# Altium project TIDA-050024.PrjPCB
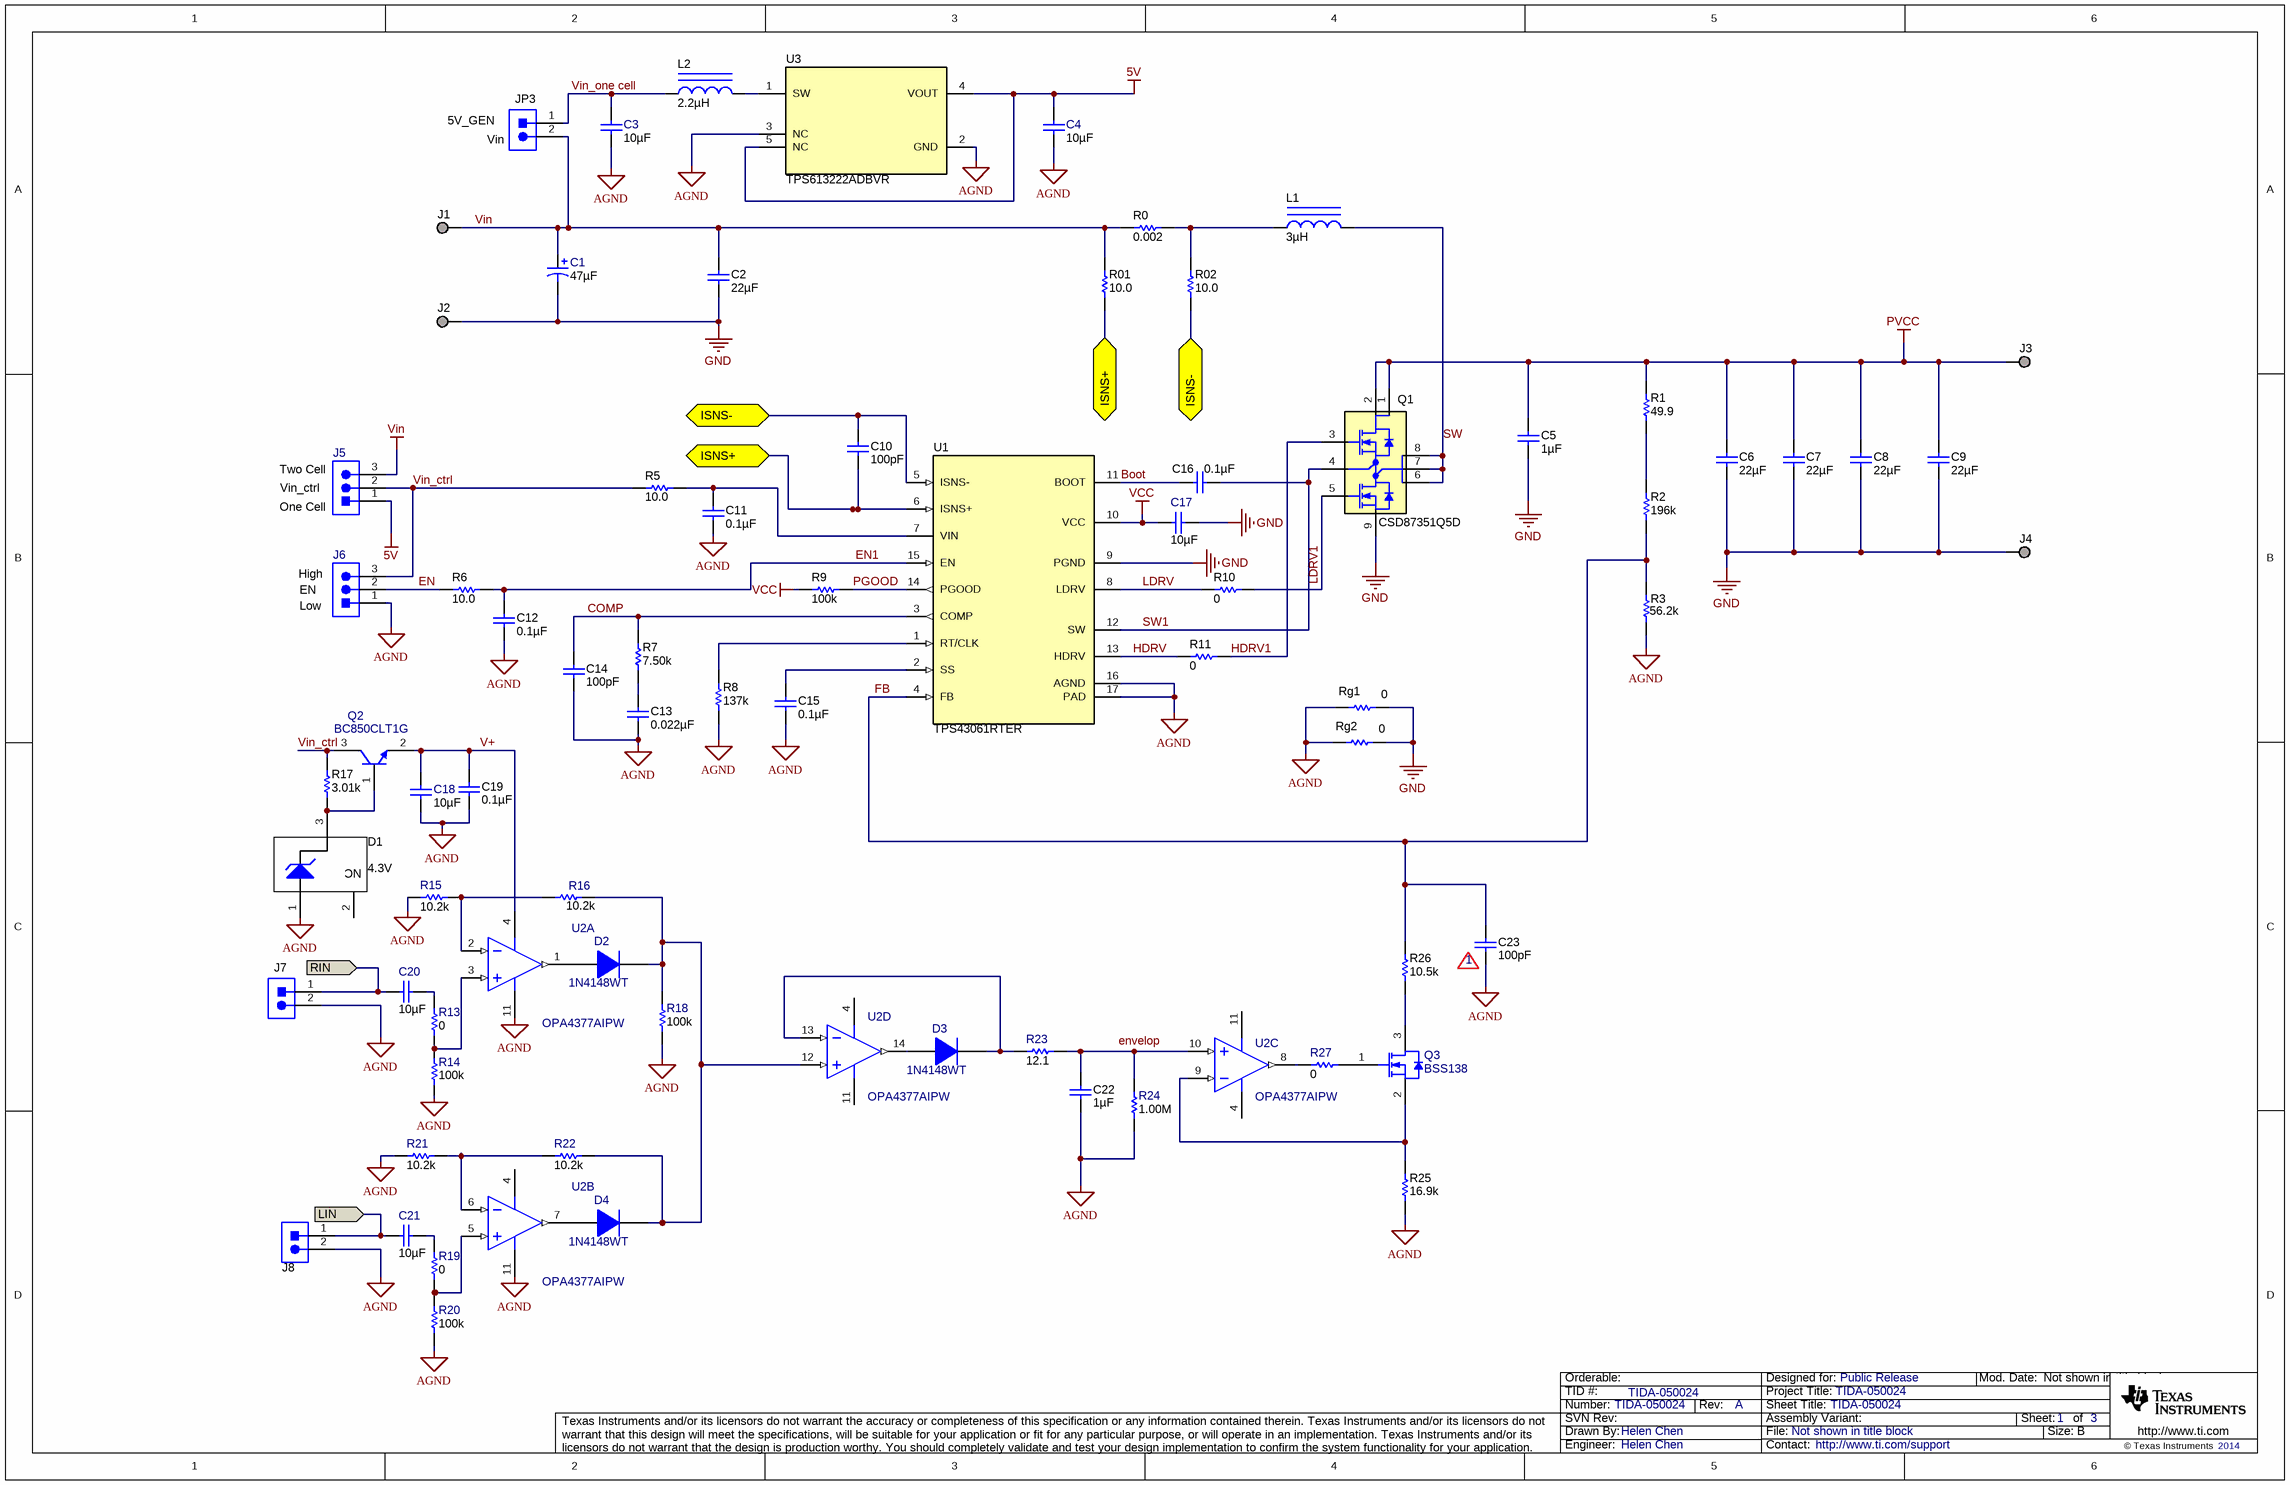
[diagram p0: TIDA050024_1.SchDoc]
TID: TIDA-050024; TechSupport: http://www.ti.com/support; SCH_Rev: A; PRJ_Title: TIDA-050024; PRJ_Number: TIDA-050024; PRJ_Engineer: Helen Chen; PRJ_Customer: Public Release; PCB_Rev: A; PCB_Layout: Helen Chen; CopyrightYear: 2014
3 sheets, 154 parts. Net scope: flat (ports and power ports of the same name join across sheets).
Board file: TIDA050024.PcbDoc
Sheets:
  TIDA050024_1.SchDoc
  TIDA050024_2.SchDoc
  TIDA050024_Hardware.SchDoc

## Sheet TIDA050024_1.SchDoc: TIDA-050024
size 431 x 279 mm; Date: Not shown in title block; ApprovedBy: Not shown in title block; CheckedBy: Not shown in title block; Author: Not shown in title block; CompanyName: TI; DrawnBy: Helen Chen; Engineer: Not shown in title block; Organization: Not shown in title block; Address1: Not shown in title block; Address2: Not shown in title block; Address3: Not shown in title block; Address4: Not shown in title block; DocumentNumber: 1; Revision: A; SheetNumber: 1; SheetTotal: 3; PageSetup: Record=PageOptions¦CenterHorizontal=True¦CenterVertical=True¦PrintScale=0.68¦XCorrection=1.00¦YCorrection=1.00¦PrintKind=0¦BorderSize=5000000¦LeftOffset=0¦BottomOffset=0¦Orientation=2¦PaperLength=1000¦PaperWidth=1000¦Scale=100¦PaperSource=15¦PrintQuality=600¦MediaType=1¦DitherType=10¦PaperKind=Letter¦PrintScaleMode=1

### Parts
C1  ValueDisplayed: 47µF  [7343-31]  (hidden comment: T495D476M025ATE120)
C2  ValueDisplayed: 22µF  [1210_270]  (hidden comment: GRM32ER61E226KE15L)
C3  ValueDisplayed: 10µF  [0603]  (hidden comment: GRM188R61E106MA73D)
C4  ValueDisplayed: 10µF  [0603]  (hidden comment: GRM188R61E106MA73D)
C5  ValueDisplayed: 1µF  [0402]  (hidden comment: C1005X5R1E105K050BC)
C6  ValueDisplayed: 22µF  [1210_270]  (hidden comment: GRM32ER61E226KE15L)
C7  ValueDisplayed: 22µF  [1210_270]  (hidden comment: GRM32ER61E226KE15L)
C8  ValueDisplayed: 22µF  [1210_270]  (hidden comment: GRM32ER61E226KE15L)
C9  ValueDisplayed: 22µF  [1210_270]  (hidden comment: GRM32ER61E226KE15L)
C10  ValueDisplayed: 100pF  [0402]  (hidden comment: GRM1555C1H101JA01D)
C11  ValueDisplayed: 0.1µF  [0402]  (hidden comment: CGA2B3X7R1H104K050BB)
C12  ValueDisplayed: 0.1µF  [0402]  (hidden comment: CGA2B3X7R1H104K050BB)
C13  ValueDisplayed: 0.022µF  [0402]  (hidden comment: GCM155R71E223KA55D)
C14  ValueDisplayed: 100pF  [0402]  (hidden comment: GRM1555C1H101JA01D)
C15  ValueDisplayed: 0.1µF  [0402]  (hidden comment: CGA2B3X7R1H104K050BB)
C16  ValueDisplayed: 0.1µF  [0402]  (hidden comment: CGA2B3X7R1H104K050BB)
C17  ValueDisplayed: 10µF  [0603]  (hidden comment: GRM188R61E106MA73D)
C18  ValueDisplayed: 10µF  [0603]  (hidden comment: GRM188R61E106MA73D)
C19  ValueDisplayed: 0.1µF  [0402]  (hidden comment: CGA2B3X7R1H104K050BB)
C20  ValueDisplayed: 10µF  [0603]  (hidden comment: GRM188R61E106MA73D)
C21  ValueDisplayed: 10µF  [0603]  (hidden comment: GRM188R61E106MA73D)
C22  ValueDisplayed: 1µF  [0402]  (hidden comment: C1005X5R1E105K050BC)
C23  ValueDisplayed: 100pF  [0402]  (hidden comment: GRM1555C1H101JA01D)
D1  value 4.3V  [SOT-23]  (hidden comment: BZX84C4V3LT1G)
D2  1N4148WT  [Fairchild_SOD-523F]
D3  1N4148WT  [Fairchild_SOD-523F]
D4  1N4148WT  [Fairchild_SOD-523F]
J1  1502-2  [Keystone1502-2]  (value not drawn)
J2  1502-2  [Keystone1502-2]  (value not drawn)
J3  1502-2  [Keystone1502-2]  (value not drawn)
J4  1502-2  [Keystone1502-2]  (value not drawn)
J5  TSW-103-07-G-S  [TSW-103-07-G-S]  (value not drawn)
J6  TSW-103-07-G-S  [TSW-103-07-G-S]  (value not drawn)
J7  TSW-102-07-G-S  [TSW-102-07-G-S]  (value not drawn)
J8  TSW-102-07-G-S  [TSW-102-07-G-S]  (value not drawn)
JP3  TSW-102-07-G-S  [TSW-102-07-G-S]  (value not drawn)
L1  ValueDisplayed: 3µH  [XAL1350]  (hidden comment: XAL1350-302MEB)
L2  ValueDisplayed: 2.2µH  [DFE252012C]  (hidden comment: DFE252012F-2R2M=P2)
Q1  CSD87351Q5D  [DQY0008A]
Q2  BC850CLT1G  [SOT-23]
Q3  BSS138  [SOT-23]
R0  ValueDisplayed: 0.002  [2512]  (hidden comment: CSNL2512FT2L00)
R01  ValueDisplayed: 10.0  [0402]  (hidden comment: CRCW040210R0FKED)
R1  ValueDisplayed: 49.9  [0402]  (hidden comment: CRCW040249R9FKED)
R02  ValueDisplayed: 10.0  [0402]  (hidden comment: CRCW040210R0FKED)
R2  ValueDisplayed: 196k  [0402]  (hidden comment: CRCW0402196KFKED)
R3  ValueDisplayed: 56.2k  [0402]  (hidden comment: CRCW040256K2FKED)
R5  ValueDisplayed: 10.0  [0402]  (hidden comment: CRCW040210R0FKED)
R6  ValueDisplayed: 10.0  [0402]  (hidden comment: CRCW040210R0FKED)
R7  ValueDisplayed: 7.50k  [0402]  (hidden comment: CRCW04027K50FKED)
R8  ValueDisplayed: 137k  [0402]  (hidden comment: CRCW0402137KFKED)
R9  ValueDisplayed: 100k  [0402]  (hidden comment: CRCW0402100KFKED)
R10  ValueDisplayed: 0  [0603]  (hidden comment: RCS06030000Z0EA)
R11  ValueDisplayed: 0  [0603]  (hidden comment: RCS06030000Z0EA)
R13  ValueDisplayed: 0  [0402]  (hidden comment: CRCW04020000Z0ED)
R14  ValueDisplayed: 100k  [0402]  (hidden comment: CRCW0402100KDHEDP)
R15  ValueDisplayed: 10.2k  [0402]  (hidden comment: CRCW040210K2FKED)
R16  ValueDisplayed: 10.2k  [0402]  (hidden comment: CRCW040210K2FKED)
R17  ValueDisplayed: 3.01k  [0402]  (hidden comment: CRCW04023K01FKED)
R18  ValueDisplayed: 100k  [0402]  (hidden comment: CRCW0402100KDHEDP)
R19  ValueDisplayed: 0  [0402]  (hidden comment: CRCW04020000Z0ED)
R20  ValueDisplayed: 100k  [0402]  (hidden comment: CRCW0402100KDHEDP)
R21  ValueDisplayed: 10.2k  [0402]  (hidden comment: CRCW040210K2FKED)
R22  ValueDisplayed: 10.2k  [0402]  (hidden comment: CRCW040210K2FKED)
R23  ValueDisplayed: 12.1  [0402]  (hidden comment: CRCW040212R1FKED)
R24  ValueDisplayed: 1.00M  [0402]  (hidden comment: ERJ-2RKF1004X)
R25  ValueDisplayed: 16.9k  [0402]  (hidden comment: CRCW040216K9FKED)
R26  ValueDisplayed: 10.5k  [0603]  (hidden comment: CRCW060310K5FKEA)
R27  ValueDisplayed: 0  [0402]  (hidden comment: CRCW04020000Z0ED)
Rg1  ValueDisplayed: 0  [0402]  (hidden comment: CRCW04020000Z0ED)
Rg2  ValueDisplayed: 0  [0402]  (hidden comment: CRCW04020000Z0ED)
U1  TPS43061RTER  [RTE0016E]
U2  OPA4377AIPW  [PW0014A_N]  (parts A,B,C,D of 4)
U3  TPS613222ADBVR  [DBV0005A_N]

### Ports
ISNS+ (bidir), ISNS- (bidir), LIN (in), RIN (in)

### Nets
5V: C4.1 J5.1 U3.4(VOUT) U3.5(NC)
AGND: C3.2 C4.2 C11.2 C12.2 C13.2 C14.2 C15.2 C18.2 C19.2 C22.2 C23.2 D1.1(A) J6.1 J7.2 J8.2 R3.1 R8.1 R14.1 R15.1 R18.1 R20.1 R21.1 R24.1 R25.1 Rg1.1 Rg2.1 U1.16(AGND) U1.17(PAD) U2.11(V-) U3.2(GND) U3.3(NC)
GND: C1.2(-) C2.2 C5.2 C6.2 C7.2 C8.2 C9.2 C17.2 J2.1 J4.1 Q1.9(PGND) Rg1.2 Rg2.2 U1.9(PGND)
PVCC: C5.1 C6.1 C7.1 C8.1 C9.1 J3.1 Q1.1(VIN) Q1.2(VIN) R1.2
VCC: C17.1 R9.1 U1.10(VCC)
Vin: C1.1(+) C2.1 J1.1 J5.3 JP3.2 R0.1 R01.2
Boot: C16.2 U1.11(BOOT)
COMP: C14.1 R7.2 U1.3(COMP)
EN: J6.2 R6.2
EN1: C12.1 R6.1 U1.15(EN)
FB: C23.1 R2.1 R3.2 R26.2 U1.4(FB)
HDRV: R11.1 U1.13(HDRV)
HDRV1: Q1.3(TG) R11.2
ISNS+: C10.2 R01.1 U1.6(ISNS+) ; port ISNS+
ISNS-: C10.1 R02.1 U1.5(ISNS-) ; port ISNS-
LDRV: R10.1 U1.8(LDRV)
LDRV1: Q1.5(BG) R10.2
LIN: C21.1 J8.1 ; port LIN
PGOOD: R9.2 U1.14(PGOOD)
RIN: C20.1 J7.1 ; port RIN
SW: L1.2 Q1.6(VSW) Q1.7(VSW) Q1.8(VSW)
SW1: C16.1 Q1.4(TGR) U1.12(SW)
V+: C18.1 C19.1 Q2.2(E) U2.4(V+)
Vin_ctrl: J5.2 J6.3 Q2.3(C) R5.2 R17.2
Vin_one cell: C3.1 JP3.1 L2.1
NetC11_1: C11.1 R5.1 U1.7(VIN)
NetC13_1: C13.1 R7.1
NetC15_1: C15.1 U1.2(SS)
NetC20_2: C20.2 R13.2
NetC21_2: C21.2 R19.2
NetC22_1: C22.1 R23.2 R24.2 U2.10(IN_C+)
NetD1_3: D1.3(K) Q2.1(B) R17.1
NetD2_1: D2.1(K) D4.1(K) R16.2 R18.2 R22.2 U2.12(IN_D+)
NetD2_2: D2.2(A) U2.1(OUT_A)
NetD3_1: D3.1(K) R23.1 U2.13(IN_D-)
NetD3_2: D3.2(A) U2.14(OUT_D)
NetD4_2: D4.2(A) U2.7(OUT_B)
NetL1_1: L1.1 R0.2 R02.2
NetL2_2: L2.2 U3.1(SW)
NetQ3_1: Q3.1(G) R27.1
NetQ3_2: Q3.2(S) R25.2 U2.9(IN_C-)
NetQ3_3: Q3.3(D) R26.1
NetR1_1: R1.1 R2.2
NetR8_2: R8.2 U1.1(RT/CLK)
NetR13_1: R13.1 R14.2 U2.3(IN_A+)
NetR15_2: R15.2 R16.1 U2.2(IN_A-)
NetR19_1: R19.1 R20.2 U2.5(IN_B+)
NetR21_2: R21.2 R22.1 U2.6(IN_B-)
NetR27_2: R27.2 U2.8(OUT_C)

Not connected (* = marked no-connect by the designer): D1 2(NC)

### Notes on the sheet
- (near JP3) 5V_GEN
- (near JP3) Vin
- (near J5) Vin_ctrl
- (near J5) One Cell
- (near J5) Two Cell
- (near J6) High
- (near J6) EN
- (near J6) Low
- (near C23) 1
- Labels drawn without touching a wire or pin: envelop

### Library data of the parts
C1 = T495D476M025ATE120: CAP, TA, 47 µF, 25 V, +/- 20%, 0.12 ohm, SMD; Manufacturer: Kemet; Polarized: Y; CompType: Capacitor; Value: 47uF; U/M: EA; Cap_F: 0.000047; Tolerance_%: 20; VDC_V: 25; Value2: 25V; ESR_ohm: 0.12; IRMS_A: 1.006; TaMin_C: -55; TaMax_C: 125; Cap_Case: D; AEC Category: Q200
C2 C6-C9 = GRM32ER61E226KE15L: CAP, CERM, 22 µF, 25 V, +/- 10%, X5R, 1210; Manufacturer: MuRata; Polarized: N; CompType: Capacitor; Value: 22uF; U/M: EA; Cap_F: 0.000022; Tolerance_%: 10; ESR_ohm: 0.002; Value1: 0.002 ohm; VDC_V: 25; Value2: 25V; IRMS_A: 3.67; TaMin_C: -55; TaMax_C: 85; Cap_Case: 1210; SizeArea_mm2: 8; SizeAreaWB_mm2: 14.7; SizeX_mm: 3.2; SizeY_mm: 2.5; SizeZ_mm: 2.7; AEC Category: Q200
C3 C4 C17 C18 C20 C21 = GRM188R61E106MA73D: CAP, CERM, 10 µF, 25 V, +/- 20%, X5R, 0603; Manufacturer: MuRata; Polarized: N; CompType: Capacitor; Value: 10uF; U/M: EA; Cap_F: 0.00001; Tolerance_%: 20; Value1: Unknown; VDC_V: 25; Value2: 25V; TaMin_C: -55; TaMax_C: 85; AEC Category: Q200
C5 C22 = C1005X5R1E105K050BC: CAP, CERM, 1 µF, 25 V,+/- 10%, X5R, 0402; Manufacturer: TDK; Polarized: N; CompType: Capacitor; Value: 1uF; U/M: EA; Cap_F: 0.000001; Tolerance_%: 10; VDC_V: 25; Value2: 25V; TaMin_C: -55; TaMax_C: 80; SizeArea_mm2: 0.5; SizeAreaWB_mm2: 3; SizeX_mm: 1; SizeZ_mm: 0.6; AEC Category: Q200; Green_Lifecycle: Active; Green_REACh: Passed
C10 C14 C23 = GRM1555C1H101JA01D: CAP, CERM, 100 pF, 50 V,+/- 5%, C0G/NP0, 0402; Manufacturer: MuRata; Polarized: N; CompType: Capacitor; Value: 100pF; U/M: EA; Cap_F: 0.0000000001; Tolerance_%: 5; VDC_V: 50; Value2: 50V; TaMin_C: -55; TaMax_C: 125; SizeArea_mm2: 0.5; SizeAreaWB_mm2: 3; SizeX_mm: 1; SizeZ_mm: 0.6; AEC Category: Q200; Green_Lifecycle: Active; Green_REACh: Passed
C11 C12 C15 C16 C19 = CGA2B3X7R1H104K050BB: CAP, CERM, 0.1 µF, 50 V,+/- 10%, X7R, AEC-Q200 Grade 1, 0402; Manufacturer: TDK; Polarized: N; CompType: Capacitor; Value: 0.1uF; U/M: EA; Cap_F: 0.0000001; Tolerance_%: 10; ESR_ohm: 0.039064; Value1: 0.039064 ohm; VDC_V: 50; Value2: 50V; IRMS_A: 0.814669; TaMin_C: -55; TaMax_C: 125; SizeArea_mm2: 0.5; SizeAreaWB_mm2: 3; SizeX_mm: 1; SizeZ_mm: 0.6; AEC Category: Q200; AEC Qualified: Y; Green_Lifecycle: Active; Green_REACh: Passed
C13 = GCM155R71E223KA55D: CAP, CERM, 0.022 µF, 25 V,+/- 10%, X7R, AEC-Q200 Grade 1, 0402; Manufacturer: MuRata; Polarized: N; CompType: Capacitor; Value: 0.022uF; U/M: EA; Cap_F: 0.000000022; Tolerance_%: 10; VDC_V: 25; Value2: 25V; TaMin_C: -55; TaMax_C: 125; SizeArea_mm2: 0.5; SizeAreaWB_mm2: 3; SizeX_mm: 1; SizeZ_mm: 0.6; AEC Category: Q200; AEC Qualified: Y
D1 = BZX84C4V3LT1G: Diode, Zener, 4.3 V, 225 mW, SOT-23; Manufacturer: ON Semiconductor; U/M: EA; Power_W: 0.225; Vz_V: 4.3; Value1: 0.225W; RJA_CperW: 556; SizeAreaWB_mm2: 14; SizeArea_mm2: 7.5; SizeX_mm: 2.5; SizeY_mm: 3; SizeZ_mm: 1.1; AEC Category: Q101
D2-D4 = 1N4148WT: Diode, Switching, 75 V, 0.3 A, SMD, 2-Leads, Body 1.2x0.8mm; Manufacturer: Fairchild Semiconductor; U/M: EA; Value: 75V; Value1: 0.3A; Io_A: 0.3; Vr_V: 75; TJmax_C: 150
J1-J4 = CMP-0055113-1: Terminal, Turret, TH, Double; Manufacturer: Keystone; CT: FALSE; Green_REACh: Passed; CompType: Turret Terminal; Green_Lifecycle: Active
J5 J6 = TSW-103-07-G-S: Header, 100mil, 3x1, Gold, TH; Manufacturer: Samtec; SymbolCreator: a0799628; U/M: EA
J7 J8 JP3 = TSW-102-07-G-S: Header, 100mil, 2x1, Gold, TH; Manufacturer: Samtec; SymbolCreator: a0412235; Pitch_mm: 2.54; Gender: Male; Shrouded: N; Row_Count: 1; Current_A: 6.3; Voltage_V: 550; Cert_CSA: Y
L1 = XAL1350-302MEB: Inductor, Shielded, Composite, 3 µH, 21 A, 0.0059 ohm, SMD; Manufacturer: Coilcraft; Value: 3uH; Ind_H: 3.0E-6; Imax_A: 21; Irms: 21A @ 40C rise; Isat: 37A @ 30% inductance drop; DCR_ohm: 0.0059; Value2: 21A; SizeAreaWB_mm2: 240; SizeArea_mm2: 182; SizeX_mm: 13; SizeY_mm: 14; SizeZ_mm: 5; AEC Category: Q200; AEC Qualified: N
L2 = DFE252012F-2R2M=P2: Inductor, Shielded, Powdered Iron, 2.2 µH, 2.3 A, 0.082 ohm, SMD; Manufacturer: MuRata Toko; Value: 2.2uH; Ind_H: 2.2E-6; Imax_A: 2.3; Irms: 2.3A @ 40C rise; Isat: 3.3A @ 30% inductance drop; DCR_ohm: 0.082; Value2: 2.3A; SizeAreaWB_mm2: 11.84; SizeArea_mm2: 5.94; SizeX_mm: 2.7; SizeY_mm: 2.2; SizeZ_mm: 1.2; AEC Category: Q200; AEC Qualified: N
Q1 = CSD87351Q5D: MOSFET, 2-CH, N-CH, 30 V, 35 A, DQY0008A (LSON-CLIP-8); Manufacturer: Texas Instruments; Alternate Manufacturer: None; SymbolCreator: a0799628; U/M: EA; ChType: N; Value: 30V; VdsMax_V: 30; Value1: 0.0088 ohm; Rdson45_ohm: 0.0088; Value2: 5.9 nC; QgTyp_nC: 5.9; Vgs_V: 10; IdsMax_A: 35; SizeAreaWB_mm2: 56; SizeX_mm: 6; SizeY_mm: 5; SizeZ_mm: 1.6; AEC Category: Q101
Q2 = BC850CLT1G, ON Semiconductor: Transistor, NPN, 45 V, 0.1 A, SOT-23; CompType: BJT; PNP: 0; NPN: 1; Vceo_V: 45; Vcesat1_V: 0.7; Value: 45 V; IcRated_A: 0.1; Value1: 0.1 A; HfeMax: 800; TaMin_C: -55; TaMax_C: 150; U/M: EA
Q3 = BSS138: MOSFET, N-CH, 50 V, 0.22 A, SOT-23; Manufacturer: Fairchild Semiconductor; Alternate Manufacturer: None; U/M: EA; ChType: N; Value: 50V; VdsMax_V: 50; Value1: 6 ohm; Rdson45_ohm: 6; Value2: 1.7 nC; QgTyp_nC: 1.7; Vgs_V: 20; IdsMax_A: 0.22
R0 = CSNL2512FT2L00: RES, 0.002, 1%, 2 W, 2512; Manufacturer: Stackpole Electronics Inc; CompType: Resistor; Value: 0.002; Value_Code: 2L000; Tolerance_%: 1; Power_W: 2; Value2: 2W; VDC_V: 200; TempCo: 50 ppm/C; SizeArea_mm2: 20.16; SizeX_mm: 6.3; SizeY_mm: 3.2; SizeZ_mm: 0.71; U/M: EA; AEC Category: Q200
R01 R02 R5 R6 = CRCW040210R0FKED: RES, 10.0, 1%, 0.063 W, 0402; Manufacturer: Vishay-Dale; CompType: Resistor; Value: 10.0; Res_ohm: 10; Value_Code: 10R0; Tolerance_%: 1; Power_W: 0.063; Value2: 0.063W; VDC_V: 50; TempCo: 100 ppm/C; SizeArea_mm2: 0.5; SizeZ_mm: 0.6; EIA_Code: E96; U/M: EA; AEC Category: Q200; Green_Lifecycle: Active; Green_REACh: Passed
R1 = CRCW040249R9FKED: RES, 49.9, 1%, 0.063 W, 0402; Manufacturer: Vishay-Dale; CompType: Resistor; Value: 49.9; Value_Code: 49R9; Tolerance_%: 1; Power_W: 0.063; Value2: 0.063W; VDC_V: 50; TempCo: 100 ppm/C; SizeArea_mm2: 0.5; SizeZ_mm: 0.6; EIA_Code: E96; U/M: EA; AEC Category: Q200; Green_Lifecycle: Active; Green_REACh: Passed
R2 = CRCW0402196KFKED: RES, 196 k, 1%, 0.063 W, 0402; Manufacturer: Vishay-Dale; CompType: Resistor; Value: 196k; Res_ohm: 196000; Tolerance_%: 1; Power_W: 0.063; Value2: 0.063W; VDC_V: 50; TempCo: 100 ppm/C; SizeArea_mm2: 0.5; SizeZ_mm: 0.6; EIA_Code: E96; U/M: EA; AEC Category: Q200; Green_Lifecycle: Active; Green_REACh: Passed
R3 = CRCW040256K2FKED: RES, 56.2 k, 1%, 0.063 W, 0402; Manufacturer: Vishay-Dale; CompType: Resistor; Value: 56.2k; Res_ohm: 56200; Value_Code: 56k2; Tolerance_%: 1; Power_W: 0.063; Value2: 0.063W; VDC_V: 50; TempCo: 100 ppm/C; SizeArea_mm2: 0.5; SizeZ_mm: 0.6; EIA_Code: E96; U/M: EA; AEC Category: Q200; Green_Lifecycle: Active; Green_REACh: Passed
R7 = CRCW04027K50FKED: RES, 7.50 k, 1%, 0.063 W, 0402; Manufacturer: Vishay-Dale; CompType: Resistor; Value: 7.50k; Res_ohm: 7500; Value_Code: 7k50; Tolerance_%: 1; Power_W: 0.063; Value2: 0.063W; VDC_V: 50; TempCo: 100 ppm/C; SizeArea_mm2: 0.5; SizeZ_mm: 0.6; EIA_Code: E96; U/M: EA; AEC Category: Q200; Green_Lifecycle: Active; Green_REACh: Passed
R8 = CRCW0402137KFKED: RES, 137 k, 1%, 0.063 W, 0402; Manufacturer: Vishay-Dale; CompType: Resistor; Value: 137k; Res_ohm: 137000; Tolerance_%: 1; Power_W: 0.063; Value2: 0.063W; VDC_V: 50; TempCo: 100 ppm/C; SizeArea_mm2: 0.5; SizeZ_mm: 0.6; EIA_Code: E96; U/M: EA; AEC Category: Q200; Green_Lifecycle: Active; Green_REACh: Passed
R9 = CRCW0402100KFKED: RES, 100 k, 1%, 0.063 W, 0402; Manufacturer: Vishay-Dale; CompType: Resistor; Value: 100k; Res_ohm: 100000; Tolerance_%: 1; Power_W: 0.063; Value2: 0.063W; VDC_V: 50; TempCo: 100 ppm/C; SizeArea_mm2: 0.5; SizeZ_mm: 0.6; EIA_Code: E96; U/M: EA; AEC Category: Q200; Green_Lifecycle: Active; Green_REACh: Passed
R10 = CMP-0081973-1: RES, 0, 0%, 0.25 W, AEC-Q200 Grade 0, 0603; Manufacturer: Vishay-Dale; SizeAreaWB_mm2: 4.68; SizeArea_mm2: 1.28; AEC Qualified: Y; AEC Category: Q200; Value: 0; SizeZ_mm: 1; SizeY_mm: 0.8; Power_W: 250mW; Value2: 0.25W; CompType: Resistor; SizeX_mm: 1.6
R11 = CMP-0081973-1: RES, 0, 0%, 0.25 W, AEC-Q200 Grade 0, 0603; Manufacturer: Vishay-Dale; SizeAreaWB_mm2: 4.68; SizeArea_mm2: 1.28; AEC Qualified: Y; AEC Category: Q200; Value: 0; SizeZ_mm: 1; SizeY_mm: 0.8; Power_W: 250mW; Value2: 0.25W; SizeX_mm: 1.6
R13 R19 R27 = CRCW04020000Z0ED: RES, 0, 5%, 0.063 W, 0402; Manufacturer: Vishay-Dale; CompType: Resistor; Value: 0; Value_Code: 0000; Tolerance_%: 5; Power_W: 0.063; Value2: 0.063W; VDC_V: 50; TempCo: 200 ppm/C; EIA_Code: E24; U/M: EA
R14 R18 R20 = CRCW0402100KDHEDP: RES, 100 k, 0.5%, 0.063 W, 0402; Manufacturer: Vishay-Dale; CompType: Resistor; Value: 100k; Res_ohm: 100000; Tolerance_%: 0.5; Power_W: 0.063; Value2: 0.063W; VDC_V: 50; TempCo: 50 ppm/C; EIA_Code: E192; U/M: EA
R15 R16 R21 R22 = CRCW040210K2FKED: RES, 10.2 k, 1%, 0.063 W, 0402; Manufacturer: Vishay-Dale; CompType: Resistor; Value: 10.2k; Res_ohm: 10200; Value_Code: 10k2; Tolerance_%: 1; Power_W: 0.063; Value2: 0.063W; VDC_V: 50; TempCo: 100 ppm/C; EIA_Code: E96; U/M: EA
R17 = CRCW04023K01FKED: RES, 3.01 k, 1%, 0.063 W, 0402; Manufacturer: Vishay-Dale; CompType: Resistor; Value: 3.01k; Res_ohm: 3010; Value_Code: 3k01; Tolerance_%: 1; Power_W: 0.063; Value2: 0.063W; VDC_V: 50; TempCo: 100 ppm/C; SizeArea_mm2: 0.5; SizeZ_mm: 0.6; EIA_Code: E96; U/M: EA; AEC Category: Q200
R23 = CRCW040212R1FKED: RES, 12.1, 1%, 0.063 W, 0402; Manufacturer: Vishay-Dale; CompType: Resistor; Value: 12.1; Value_Code: 12R1; Tolerance_%: 1; Power_W: 0.063; Value2: 0.063W; VDC_V: 50; TempCo: 100 ppm/C; EIA_Code: E96; U/M: EA
R24 = ERJ-2RKF1004X: RES, 1.00 M, 1%, 0.1 W, 0402; Manufacturer: Panasonic; CompType: Resistor; Value: 1.00Meg; Res_ohm: 1000000; Value_Code: 1M00; Tolerance_%: 1; Power_W: 0.1; Value2: 0.1W; VDC_V: 50; TempCo: 100 ppm/C; EIA_Code: E96; U/M: EA
R25 = CRCW040216K9FKED: RES, 16.9 k, 1%, 0.063 W, 0402; Manufacturer: Vishay-Dale; CompType: Resistor; Value: 16.9k; Res_ohm: 16900; Value_Code: 16k9; Tolerance_%: 1; Power_W: 0.063; Value2: 0.063W; VDC_V: 50; TempCo: 100 ppm/C; SizeArea_mm2: 0.5; SizeZ_mm: 0.6; EIA_Code: E96; U/M: EA; AEC Category: Q200
R26 = CRCW060310K5FKEA: RES, 10.5 k, 1%, 0.1 W, 0603; Manufacturer: Vishay-Dale; CompType: Resistor; Value: 10.5k; Res_ohm: 10500; Value_Code: 10k5; Tolerance_%: 1; Power_W: 0.1; Value2: 0.1W; VDC_V: 75; TempCo: 100 ppm/C; SizeArea_mm2: 1.28; SizeX_mm: 1.6; SizeY_mm: 0.8; EIA_Code: E96; U/M: EA; AEC Category: Q200; Green_Lifecycle: Active; Green_REACh: Passed
Rg1 Rg2 = CRCW04020000Z0ED: RES, 0, 5%, 0.063 W, 0402; Manufacturer: Vishay-Dale; CompType: Resistor; Value: 0; Value_Code: 0000; Tolerance_%: 5; Power_W: 0.063; Value2: 0.063W; VDC_V: 50; TempCo: 200 ppm/C; SizeArea_mm2: 0.5; SizeX_mm: 1; SizeZ_mm: 0.6; EIA_Code: E24; U/M: EA; AEC Category: Q200; Green_Lifecycle: Active; Green_REACh: Passed
U1 = CMP-0067158-1: Low Iq, Synchronous Boost Controller with Wide Input Voltage and 5.5V Gate Drive for Low Qg  NexFETs, RTE0016E (WQFN-16); Alternate PartNumber: TPS43061RTET; Alternate Manufacturer: Texas Instruments; Green_Lifecycle: Active; SizeAreaWB_mm2: 16.0; Green_REACh: Passed; U/M: EA; SizeZ_mm: 0.8; SizeX_mm: 3.0; SizeArea_mm2: 9.0; CompType: IC
U2 = OPA4377AIPW: Low-Cost, Low Noise, 5.5 MHz CMOS Operational Amplifier, 2.2 to 5.5 V, -40 to 125 degC, 14-pin SOP (PW0014A), Green (RoHS & no Sb/Br); Manufacturer: Texas Instruments; Alternate Manufacturer: None; Alternate PartNumber: Equivalent; CMRR(Min)(dB): 70; IIB(Max)(pA): 10; Iq per channel(Max)(mA): 1.05; Number of Channels: 4; Offset Drift(Typ)(uV/C): 0.32; Slew Rate(Typ)(V/us): 2; Sub Family: Low Input Bias Current Amp (<=10pA), Low Noise Amp (<=10nV/rtHz), Low Supply Voltage Amplifier (<=2.7V), Precision Amplifier; Total Supply Voltage(Max)(+5V is 5, +/-5V is 10): 5.5; Total Supply Voltage(Min)(+5V is 5, +/-5V is 10): 2.2; Vio (25C)(Max)(mV): 1; Vn at 1kHz(Typ)(nV/rtHz): 7.5
U3 = CMP-0079087-1: 6.5-μA Quiescent Current, 1.8-A Switch Current Boost Converter, DBV0005A (SOT-23-5); Alternate PartNumber: TPS613222ADBVT; Alternate Manufacturer: Texas Instruments; SizeAreaWB_mm2: 14.82; SizeZ_mm: 1.45; SizeX_mm: 2.8; SizeY_mm: 2.9; SizeArea_mm2: 8.12; CompType: IC; AEC Qualified: N; AEC Category: Q200

## Sheet TIDA050024_2.SchDoc: TIDA-050024
size 431 x 279 mm; Date: Not shown in title block; ApprovedBy: Not shown in title block; CheckedBy: Not shown in title block; Author: Not shown in title block; CompanyName: TI; DrawnBy: Helen Chen; Engineer: Not shown in title block; Organization: Not shown in title block; Address1: Not shown in title block; Address2: Not shown in title block; Address3: Not shown in title block; Address4: Not shown in title block; DocumentNumber: PMP15036; Revision: A; SheetNumber: 2; SheetTotal: 3; PageSetup: Record=PageOptions¦CenterHorizontal=True¦CenterVertical=True¦PrintScale=0.68¦XCorrection=1.00¦YCorrection=1.00¦PrintKind=0¦BorderSize=5000000¦LeftOffset=0¦BottomOffset=0¦Orientation=2¦PaperLength=1000¦PaperWidth=1000¦Scale=100¦PaperSource=15¦PrintQuality=-3¦MediaType=1¦DitherType=10¦PrintScaleMode=1¦PaperKind=A1 (594 x 841mm)¦PaperIndex=124
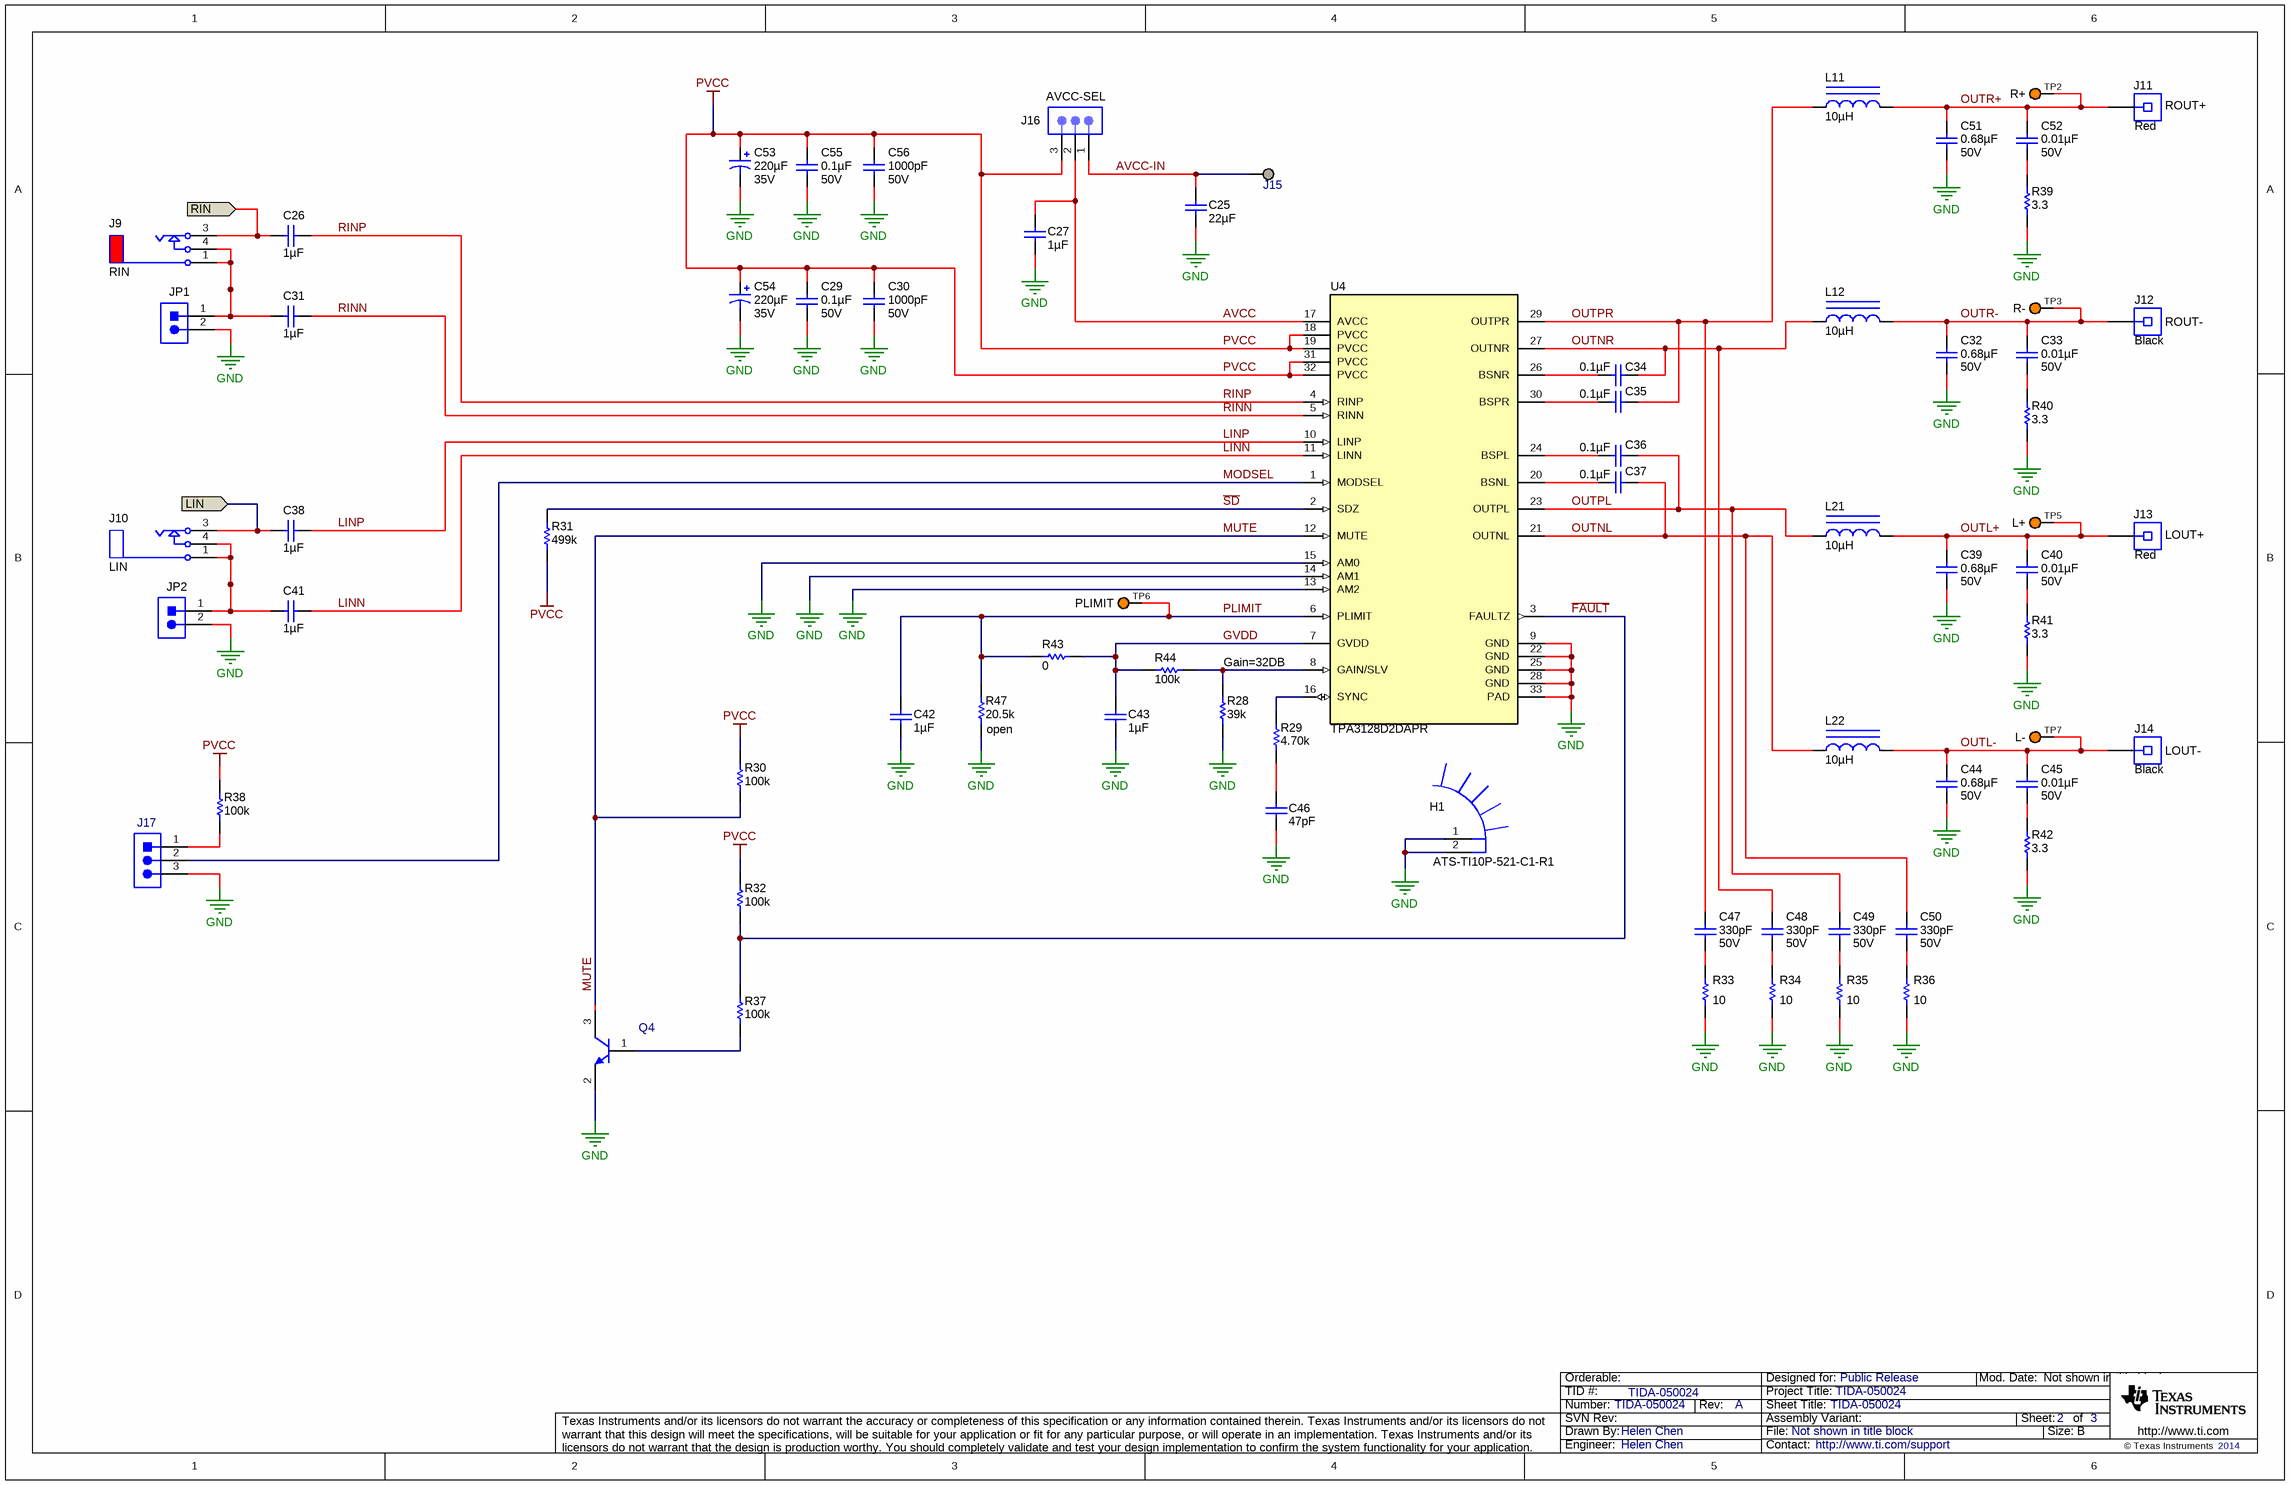
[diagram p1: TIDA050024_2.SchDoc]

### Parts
(Parts that share a designator on the sheet are numbered #1, #2 ... from top to bottom, then left to right.)
C25  ValueDisplayed: 22µF  [1210_270]  (hidden comment: GRM32ER61E226KE15L)
C26  ValueDisplayed: 1µF  [0603]  (hidden comment: GRM188R61E105KA12D)
C27  ValueDisplayed: 1µF  [0603]  (hidden comment: GRM188R61E105KA12D)
C29  ValueDisplayed: 0.1µF  Value2: 50V  [0603L]  (hidden comment: GCM188R71H104KA57D)
C30  ValueDisplayed: 1000pF  Value2: 50V  [0603L]  (hidden comment: GRM1885C1H102JA01D)
C31  ValueDisplayed: 1µF  [0603]  (hidden comment: GRM188R61E105KA12D)
C32  ValueDisplayed: 0.68µF  Value2: 50V  [1206L]  (hidden comment: GRM31MR71H684KA88L)
C33  ValueDisplayed: 0.01µF  Value2: 50V  [0603L]  (hidden comment: GRM188R71H103KA01D)
C34  ValueDisplayed: 0.1µF  [0603L]  (hidden comment: GCM188R71H104KA57D)
C35  ValueDisplayed: 0.1µF  [0603L]  (hidden comment: GCM188R71H104KA57D)
C36  ValueDisplayed: 0.1µF  [0603L]  (hidden comment: GCM188R71H104KA57D)
C37  ValueDisplayed: 0.1µF  [0603L]  (hidden comment: GCM188R71H104KA57D)
C38  ValueDisplayed: 1µF  [0603]  (hidden comment: GRM188R61E105KA12D)
C39  ValueDisplayed: 0.68µF  Value2: 50V  [1206L]  (hidden comment: GRM31MR71H684KA88L)
C40  ValueDisplayed: 0.01µF  Value2: 50V  [0603L]  (hidden comment: GRM188R71H103KA01D)
C41  ValueDisplayed: 1µF  [0603]  (hidden comment: GRM188R61E105KA12D)
C42  ValueDisplayed: 1µF  [0603]  (hidden comment: GRM188R61E105KA12D)
C43  ValueDisplayed: 1µF  [0603]  (hidden comment: GRM188R61E105KA12D)
C44  ValueDisplayed: 0.68µF  Value2: 50V  [1206L]  (hidden comment: GRM31MR71H684KA88L)
C45  ValueDisplayed: 0.01µF  Value2: 50V  [0603L]  (hidden comment: GRM188R71H103KA01D)
C46  ValueDisplayed: 47pF  [0603L]  (hidden comment: GRM1885C1H470JA01D)
C47  ValueDisplayed: 330pF  Value2: 50V  [0603L]  (hidden comment: GRM1885C1H331JA01D)
C48  ValueDisplayed: 330pF  Value2: 50V  [0603L]  (hidden comment: GRM1885C1H331JA01D)
C49  ValueDisplayed: 330pF  Value2: 50V  [0603L]  (hidden comment: GRM1885C1H331JA01D)
C50  ValueDisplayed: 330pF  Value2: 50V  [0603L]  (hidden comment: GRM1885C1H331JA01D)
C51  ValueDisplayed: 0.68µF  Value2: 50V  [1206L]  (hidden comment: GRM31MR71H684KA88L)
C52  ValueDisplayed: 0.01µF  Value2: 50V  [0603L]  (hidden comment: GRM188R71H103KA01D)
C53  ValueDisplayed: 220µF  Value2: 35V  [FC_1000x1250]  (hidden comment: EEU-FC1V221)
C54  ValueDisplayed: 220µF  Value2: 35V  [FC_1000x1250]  (hidden comment: EEU-FC1V221)
C55  ValueDisplayed: 0.1µF  Value2: 50V  [0603L]  (hidden comment: GCM188R71H104KA57D)
C56  ValueDisplayed: 1000pF  Value2: 50V  [0603L]  (hidden comment: GRM1885C1H102JA01D)
H1#1  ATS-TI10P-521-C1-R1  [HSINK_ATS-TI10P-521-C1-R1]
J9  RIN  [Keystone_971]
J10  LIN  [Keystone_970]
J11  ROUT+  Shell Color: Red  [Keystone_7006]
J12  ROUT-  Shell Color: Black  [Keystone_7007]
J13  LOUT+  Shell Color: Red  [Keystone_7006]
J14  LOUT-  Shell Color: Black  [Keystone_7007]
J15  Suggest using a net name here  [Keystone1502-2]  (value not drawn)
J16  AVCC-SEL  [PBC03SAAN]
J17  TSW-103-07-G-S  [TSW-103-07-G-S]  (value not drawn)
JP1  TSW-102-07-G-S  [TSW-102-07-G-S]  (value not drawn)
JP2  TSW-102-07-G-S  [TSW-102-07-G-S]  (value not drawn)
L11  ValueDisplayed: 10µH  [SRT8045]  (hidden comment: SRT8045-103MEB)
L12  ValueDisplayed: 10µH  [SRT8045]  (hidden comment: SRT8045-103MEB)
L21  ValueDisplayed: 10µH  [SRT8045]  (hidden comment: SRT8045-103MEB)
L22  ValueDisplayed: 10µH  [SRT8045]  (hidden comment: SRT8045-103MEB)
Q4  BC850CLT1G  [SOT-23]  (value not drawn)
R28  ValueDisplayed: 39k  [0402]  (hidden comment: CRCW040239K0JNED)
R29  ValueDisplayed: 4.70k  [0603L]  (hidden comment: RG1608P-472-B-T5)
R30  value 100k  [0603L]  (hidden comment: RC0603FR-07100KL)
R31  ValueDisplayed: 499k  [0603L]  (hidden comment: RC0603FR-07499KL)
R32  value 100k  [0603L]  (hidden comment: RC0603FR-07100KL)
R33  ValueDisplayed: 10  [0805_KTR]  (hidden comment: CRCW080510R0JNEA)
R34  ValueDisplayed: 10  [0805_KTR]  (hidden comment: CRCW080510R0JNEA)
R35  ValueDisplayed: 10  [0805_KTR]  (hidden comment: CRCW080510R0JNEA)
R36  ValueDisplayed: 10  [0805_KTR]  (hidden comment: CRCW080510R0JNEA)
R37  value 100k  [0603L]  (hidden comment: RC0603FR-07100KL)
R38  value 100k  [0603L]  (hidden comment: RC0603FR-07100KL)
R39  ValueDisplayed: 3.3  [0603L]  (hidden comment: CRCW06033R30JNEA)
R40  ValueDisplayed: 3.3  [0603L]  (hidden comment: CRCW06033R30JNEA)
R41  ValueDisplayed: 3.3  [0603L]  (hidden comment: CRCW06033R30JNEA)
R42  ValueDisplayed: 3.3  [0603L]  (hidden comment: CRCW06033R30JNEA)
R43  ValueDisplayed: 0  [0402]  (hidden comment: ERJ-2GE0R00X)
R44  value 100k  [0603L]  (hidden comment: RC0603FR-07100KL)
R47  ValueDisplayed: 20.5k  [0402]  (hidden comment: CRCW040220K5FKED)
TP2  R+  [Keystone5003]
TP3  R-  [Keystone5003]
TP5  L+  [Keystone5003]
TP6  PLIMIT  [Keystone5003]
TP7  L-  [Keystone5003]
U4  TPA3128D2DAPR  [DAP0032A_N]

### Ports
LIN (in), RIN (in)

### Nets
GND: C25.2 C27.2 C29.1 C30.1 C32.2 C39.2 C42.1 C43.1 C44.2 C46.2 C51.2 C53.2(-) C54.2(-) C55.1 C56.1 H1#1.1 H1#1.2 J17.3 JP1.2 JP2.2 Q4.2(E) R28.1 R33.1 R34.1 R35.1 R36.1 R39.1 R40.1 R41.1 R42.1 R47.1 U4.9(GND) U4.13(AM2) U4.14(AM1) U4.15(AM0) U4.22(GND) U4.25(GND) U4.28(GND) U4.33(PAD)
PVCC: C29.2 C30.2 C53.1(+) C54.1(+) C55.2 C56.2 J16.3 R30.1 R31.2 R32.1 R38.2 U4.18(PVCC) U4.19(PVCC) U4.31(PVCC) U4.32(PVCC)
~{FAULT}: R32.2 R37.1 U4.3(FAULTZ)
~{SD}: R31.1 U4.2(SDZ)
AVCC: C27.1 J16.2 U4.17(AVCC)
AVCC-IN: C25.1 J15.1 J16.1
GVDD: C43.2 R43.2 R44.1 U4.7(GVDD)
LIN: C38.1 J10.3(TIP) ; port LIN
LINN: C41.2 U4.11(LINN)
LINP: C38.2 U4.10(LINP)
MODSEL: J17.2 U4.1(MODSEL)
MUTE: Q4.3(C) R30.2 U4.12(MUTE)
OUTL+: C39.1 C40.1 J13.1 L21.2 TP5.1
OUTL-: C44.1 C45.1 J14.1 L22.2 TP7.1
OUTNL: C37.1 C50.2 L22.1 U4.21(OUTNL)
OUTNR: C34.1 C48.2 L12.1 U4.27(OUTNR)
OUTPL: C36.1 C49.2 L21.1 U4.23(OUTPL)
OUTPR: C35.1 C47.2 L11.1 U4.29(OUTPR)
OUTR+: C51.1 C52.1 J11.1 L11.2 TP2.1
OUTR-: C32.1 C33.1 J12.1 L12.2 TP3.1
PLIMIT: C42.2 R43.1 R47.2 TP6.1 U4.6(PLIMIT)
RIN: C26.1 J9.3(TIP) ; port RIN
RINN: C31.2 U4.5(RINN)
RINP: C26.2 U4.4(RINP)
NetC31_1: C31.1 J9.1(SLEEVE) J9.4(TIP_SWITCH) JP1.1
NetC33_2: C33.2 R40.2
NetC34_2: C34.2 U4.26(BSNR)
NetC35_2: C35.2 U4.30(BSPR)
NetC36_2: C36.2 U4.24(BSPL)
NetC37_2: C37.2 U4.20(BSNL)
NetC40_2: C40.2 R41.2
NetC41_1: C41.1 J10.1(SLEEVE) J10.4(TIP_SWITCH) JP2.1
NetC45_2: C45.2 R42.2
NetC46_1: C46.1 R29.1
NetC47_1: C47.1 R33.2
NetC48_1: C48.1 R34.2
NetC49_1: C49.1 R35.2
NetC50_1: C50.1 R36.2
NetC52_2: C52.2 R39.2
NetJ17_1: J17.1 R38.1
NetQ4_1: Q4.1(B) R37.2
NetR28_2: R28.2 R44.2 U4.8(GAIN/SLV)
NetR29_2: R29.2 U4.16(SYNC)

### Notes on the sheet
- Gain=32DB
- (near R47) open

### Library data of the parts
C25 = GRM32ER61E226KE15L: as C2 on sheet TIDA050024_1
C26 C27 C31 C38 C41-C43 = GRM188R61E105KA12D: CAP, CERM, 1 µF, 25 V, +/- 10%, X5R, 0603; Manufacturer: MuRata; Polarized: N; CompType: Capacitor; Value: 1uF; U/M: EA; Cap_F: 0.000001; Tolerance_%: 10; Value1: Unknown; VDC_V: 25; Value2: 25V; TaMin_C: -55; TaMax_C: 85; SizeArea_mm2: 1.28; SizeAreaWB_mm2: 4.68; SizeX_mm: 1.6; SizeY_mm: 0.8; SizeZ_mm: 1; AEC Category: Q200; Green_Lifecycle: Active; Green_REACh: Passed
C29 C55 = GCM188R71H104KA57D: CAP, CERM, 0.1 µF, 50 V, +/- 10%, X7R, 0603; Manufacturer: MuRata; Polarized: N; CompType: Capacitor; Value: 0.1uF; U/M: EA; Cap_F: 0.0000001; Tolerance_%: 10; ESR_ohm: 0.02; Value1: 0.02 ohm; VDC_V: 50; IRMS_A: 1.84; TaMin_C: -55; TaMax_C: 125; Cap_Case: 0603
C30 C56 = GRM1885C1H102JA01D: CAP, CERM, 1000 pF, 50 V, +/- 5%, C0G/NP0, 0603; Manufacturer: MuRata; Polarized: N; CompType: Capacitor; Value: 1000pF; U/M: EA; Cap_F: 0.000000001; Tolerance_%: 5; Value1: Unknown; VDC_V: 50; TaMin_C: -55; TaMax_C: 125; Cap_Case: 0603
C32 C39 C44 C51 = GRM31MR71H684KA88L: CAP, CERM, 0.68 µF, 50 V, +/- 10%, X7R, 1206; Manufacturer: MuRata; Polarized: N; CompType: Capacitor; Value: 0.68uF; U/M: EA; Cap_F: 0.00000068; Tolerance_%: 10; Value1: Unknown; VDC_V: 50; TaMin_C: -55; TaMax_C: 125; Cap_Case: 1206
C33 C40 C45 C52 = GRM188R71H103KA01D: CAP, CERM, 0.01 µF, 50 V, +/- 10%, X7R, 0603; Manufacturer: MuRata; Polarized: N; CompType: Capacitor; Value: 0.01uF; U/M: EA; Cap_F: 0.00000001; Tolerance_%: 10; Value1: Unknown; VDC_V: 50; TaMin_C: -55; TaMax_C: 125; Cap_Case: 0603
C34-C37 = GCM188R71H104KA57D: CAP, CERM, 0.1 µF, 50 V, +/- 10%, X7R, 0603; Manufacturer: MuRata; Polarized: N; CompType: Capacitor; Value: 0.1uF; U/M: EA; Cap_F: 0.0000001; Tolerance_%: 10; ESR_ohm: 0.02; Value1: 0.02 ohm; VDC_V: 50; Value2: 50V; IRMS_A: 1.84; TaMin_C: -55; TaMax_C: 125; Cap_Case: 0603
C46 = GRM1885C1H470JA01D: CAP, CERM, 47 pF, 50 V, +/- 5%, C0G/NP0, 0603; Manufacturer: MuRata; Polarized: N; CompType: Capacitor; Value: 47pF; U/M: EA; Cap_F: 0.000000000047; Tolerance_%: 5; Value1: Unknown; VDC_V: 50; Value2: 50V; TaMin_C: -55; TaMax_C: 125; Cap_Case: 0603; AEC Category: Q200
C47-C50 = GRM1885C1H331JA01D: CAP, CERM, 330 pF, 50 V, +/- 5%, C0G/NP0, 0603; Manufacturer: MuRata; Polarized: N; CompType: Capacitor; Value: 330pF; U/M: EA; Cap_F: 0.00000000033; Tolerance_%: 5; Value1: Unknown; VDC_V: 50; TaMin_C: -55; TaMax_C: 125; Cap_Case: 0603
C53 C54 = EEU-FC1V221: CAP, AL, 220 µF, 35 V, +/- 20%, 0.09 ohm, TH; Manufacturer: Panasonic; Polarized: Y; CompType: Capacitor; Value: 220uF; U/M: EA; Cap_F: 0.00022; Tolerance_%: 20; VDC_V: 35; ESR_ohm: 0.09; IRMS_A: 0.755; TaMin_C: -55; TaMax_C: 105; Cap_Case: 10x12.5
H1#1 = ATS-TI10P-521-C1-R1: Heatsink FOR TI MOD, 50x13.9mm; Manufacturer: Advanced Thermal Solutions; SymbolCreator: a0799628
J9 = 971: RCA Jack, Red, R/A, TH; Manufacturer: Keystone; SymbolCreator: Altium; CompType: Phono Jack; U/M: EA
J10 = 970: RCA Jack, White, R/A, TH; Manufacturer: Keystone; SymbolCreator: Altium; CompType: Phono Jack; U/M: EA
J11 J13 = 7006: Binding Post, RED, TH; Manufacturer: Keystone; SymbolCreator: a0799628; CompType: Connector; U/M: EA
J12 J14 = 7007: Binding Post, BLACK, TH; Manufacturer: Keystone; SymbolCreator: a0799628; CompType: Connector; U/M: EA
J15 = 1502-2: Terminal, Turret, TH, Double; Manufacturer: Keystone; CompType: Turret Terminal; U/M: EA
J16 = PBC03SAAN: Header, 100mil, 3x1, Gold, TH; Manufacturer: Sullins Connector Solutions
J17 = TSW-103-07-G-S: as J5 on sheet TIDA050024_1
JP1 JP2 = TSW-102-07-G-S: as J7 on sheet TIDA050024_1
L11 L12 L21 L22 = SRT8045-103MEB: Inductor, Shielded, Ferrite, 10 µH, 4.2 A, 0.037 ohm, AEC-Q200 Grade 1, SMD; Manufacturer: Coilcraft; Value: 10uH; Ind_H: 10.0E-6; Imax_A: 4.2; Irms: 4.2A @ 20C rise; Isat: 5.7A @ 10% inductance drop; DCR_ohm: 0.037; Value2: 4.2A; SizeAreaWB_mm2: 104; SizeArea_mm2: 67.2; SizeX_mm: 8; SizeY_mm: 8.4; SizeZ_mm: 4.6; AEC Category: Q200; AEC Qualified: Y; AEC Grade: 1
Q4 = BC850CLT1G, ON Semiconductor: as Q2 on sheet TIDA050024_1
R28 = CRCW040239K0JNED: RES, 39 k, 5%, 0.063 W, 0402; Manufacturer: Vishay-Dale; CompType: Resistor; Value: 39k; Res_ohm: 39000; Value_Code: 39k0; Tolerance_%: 5; Power_W: 0.063; Value2: 0.063W; VDC_V: 50; TempCo: 200 ppm/C; SizeArea_mm2: 0.5; SizeX_mm: 1; SizeZ_mm: 0.6; EIA_Code: E24; U/M: EA; AEC Category: Q200
R29 = RG1608P-472-B-T5: RES, 4.70 k, 0.1%, 0.1 W, 0603; Manufacturer: Susumu Co Ltd; CompType: Resistor; Value: 4.70k; Res_ohm: 4700; Value_Code: 4k70; Tolerance_%: 0.1; Value2: 0.1W; VDC_V: 75; TempCo: 25 ppm/C; EIA_Code: E192; U/M: EA; AEC Category: Q200
R30 R32 R37 R38 R44 = RC0603FR-07100KL: RES, 100k ohm, 1%, 0.1W, 0603; Manufacturer: Yageo America; CompType: Resistor; Res_ohm: 100000; Tolerance_%: 1; Power_W: 0.1; VDC_V: 150; TempCo: 200 ppm/C; EIA_Code: E96; U/M: EA
R31 = RC0603FR-07499KL: RES, 499 k, 1%, 0.1 W, 0603; Manufacturer: Yageo America; CompType: Resistor; Value: 499k; Res_ohm: 499000; Tolerance_%: 1; Power_W: 0.1; Value2: 0.1W; VDC_V: 150; TempCo: 200 ppm/C; EIA_Code: E96; U/M: EA; AEC Category: Q200
R33-R36 = CRCW080510R0JNEA: RES, 10, 5%, 0.125 W, 0805; Manufacturer: Vishay-Dale; CompType: Resistor; Value: 10; Value_Code: 10R0; Tolerance_%: 5; Power_W: 0.125; Value2: 0.125W; VDC_V: 150; TempCo: 200 ppm/C; EIA_Code: E24; U/M: EA
R39-R42 = CRCW06033R30JNEA: RES, 3.3, 5%, 0.1 W, 0603; Manufacturer: Vishay-Dale; CompType: Resistor; Value: 3.3; Value_Code: 3R30; Tolerance_%: 5; Power_W: 0.1; Value2: 0.1W; VDC_V: 75; TempCo: 200 ppm/C; EIA_Code: E24; U/M: EA
R43 = ERJ-2GE0R00X: RES, 0, 5%, 0.063 W, 0402; Manufacturer: Panasonic; CompType: Resistor; Value: 0; Value_Code: 0000; Tolerance_%: 5; Power_W: 0.063; Value2: 0.063W; VDC_V: 50; TempCo: 600 ppm/C; SizeArea_mm2: 0.5; SizeX_mm: 1; SizeZ_mm: 0.6; EIA_Code: E24; U/M: EA; AEC Category: Q200; Green_Lifecycle: Active; Green_REACh: Passed
R47 = CRCW040220K5FKED: RES, 20.5 k, 1%, 0.063 W, 0402; Manufacturer: Vishay-Dale; CompType: Resistor; Value: 20.5k; Res_ohm: 20500; Value_Code: 20k5; Tolerance_%: 1; Power_W: 0.063; Value2: 0.063W; VDC_V: 50; TempCo: 100 ppm/C; SizeArea_mm2: 0.5; SizeZ_mm: 0.6; EIA_Code: E96; U/M: EA; AEC Category: Q200
TP2 TP3 TP5-TP7 = 5003: Test Point, Miniature, Orange, TH; Manufacturer: Keystone; CompType: Test Point Loop; U/M: EA
U4 = TPA3128D2DAPR: 2x30-W Class-D Amplifier With Low Idle Power Dissipation, DAP0032A (TSSOP-32); Manufacturer: Texas Instruments; SymbolCreator: Altium; SizeArea_mm2: 89.1; SizeAreaWB_mm2: 131.3; SizeX_mm: 8.1; SizeY_mm: 11; SizeZ_mm: 1.2; CompType: IC; U/M: EA; Green_Lifecycle: Active; Green_REACh: Passed

## Sheet TIDA050024_Hardware.SchDoc
size A4; Date: Not shown in title block; ApprovedBy: Not shown in title block; CheckedBy: Not shown in title block; Author: Not shown in title block; CompanyName: Not shown in title block; Engineer: Not shown in title block; Organization: Not shown in title block; Address1: Not shown in title block; Address2: Not shown in title block; Address3: Not shown in title block; Address4: Not shown in title block; DocumentNumber: 3; Revision: Use project parameter SCH_Rev; SheetNumber: 3; SheetTotal: 3; PageSetup: Record=PageOptions¦CenterHorizontal=True¦CenterVertical=True¦PrintScale=0.69¦XCorrection=1.00¦YCorrection=1.00¦PrintKind=0¦BorderSize=5000000¦LeftOffset=0¦BottomOffset=0¦Orientation=2¦PaperLength=1000¦PaperWidth=1000¦Scale=100¦PaperSource=15¦PrintQuality=600¦MediaType=1¦DitherType=10¦PaperKind=Letter¦PrintScaleMode=1
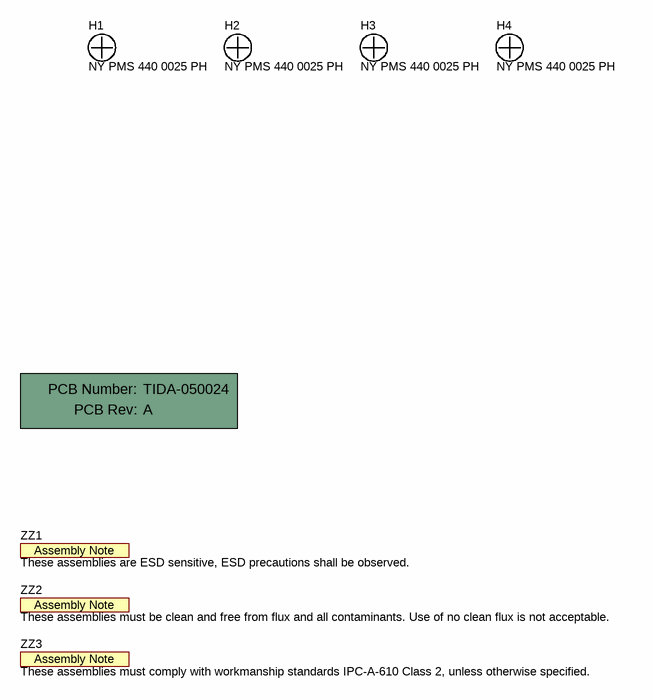
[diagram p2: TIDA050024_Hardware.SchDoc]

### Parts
(Parts that share a designator on the sheet are numbered #1, #2 ... from top to bottom, then left to right.)
!PCB1  Printed Circuit Board  (value not drawn)  (mechanical)
H1#2  NY PMS 440 0025 PH  [NY PMS 440 0025 PH]
H2  NY PMS 440 0025 PH  [NY PMS 440 0025 PH]
H3  NY PMS 440 0025 PH  [NY PMS 440 0025 PH]
H4  NY PMS 440 0025 PH  [NY PMS 440 0025 PH]
ZZ1  These assemblies are ESD sensitive, ESD precautions shall be observed.  [AssemblyNote]  (no BOM)
ZZ2  These assemblies must be clean and free from flux and all contaminants. Use of no clean flux is not acceptable.  [AssemblyNote]  (no BOM)
ZZ3  These assemblies must comply with workmanship standards IPC-A-610 Class 2, unless otherwise specified.  [AssemblyNote]  (no BOM)

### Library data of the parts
!PCB1 = PCB: Manufacturer: Any; PartNumber: TIDA-050024; SymbolCreator: a0412235
H1#2 H2-H4 = NY PMS 440 0025 PH: Machine Screw, Round, #4-40 x 1/4, Nylon, Philips panhead; Manufacturer: B&F Fastener Supply; CompType: Hardware; SymbolCreator: codlsc; U/M: EA
ZZ1-ZZ3 = AssemblyNote: SymbolCreator: codlsc

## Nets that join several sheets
GND: TIDA050024_1 (14 pins), TIDA050024_2 (39 pins)
PVCC: TIDA050024_1 (9 pins), TIDA050024_2 (15 pins)
LIN: TIDA050024_1 (C21.1 J8.1), TIDA050024_2 (C38.1 J10.3)
RIN: TIDA050024_1 (C20.1 J7.1), TIDA050024_2 (C26.1 J9.3)

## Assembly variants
one cell: not fitted R27
two cell: all parts fitted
